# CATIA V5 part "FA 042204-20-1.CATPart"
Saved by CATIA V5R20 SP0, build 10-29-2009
Part number: FA 042204-20-1
Revision: ANY
Definition: UNKNOWN
Nomenclature: FA 042204-20-1
Source: Unknown
Bounding box of the stored display mesh (mm): x -2 to 2, y 0.1 to 12.1, z -2 to 2
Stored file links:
  C:\Users\Utente\Desktop\IO LAVORO\3D X SITO CF\CUMSA\3D files FA\FA 042204-20\FA 042204-20-1.CATPart

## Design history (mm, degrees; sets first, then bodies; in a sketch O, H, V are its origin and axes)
Body1 "Cortar-Extruir3" (main body)
  Solid1: solid without history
